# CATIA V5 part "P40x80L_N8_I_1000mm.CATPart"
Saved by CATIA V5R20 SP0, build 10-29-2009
Part number: 80x40_Y-Traeger
Nomenclature: P40x80L_N8_I
Source: Unknown
Bounding box of the stored display mesh (mm): x -25.6 to 54.4, y 0 to 40, z 80 to 1000
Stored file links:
  C:\Users\Andi\Desktop\Offene Projekte\Plasmacutter\Rahmen\P40x80L_N8_I_1000mm.CATPart
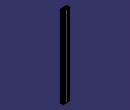
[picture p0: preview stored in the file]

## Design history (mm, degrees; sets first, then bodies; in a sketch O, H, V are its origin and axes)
Set1
  Sketch1 on face of Solid1, origin (0, 0, 0), H (1, 0, 0), V (0, -1, 0)
    projected arc E1 centre (2, -35.5) radius 2.5 from (2, -38) to (4.5, -35.5) ccw from edge [face of Solid1 | face of Solid1]
    projected arc E2 centre (2, -37.5) radius 0.5 from (1.5, -37.5) to (2, -38) ccw from edge [face of Solid1 | face of Solid1]
    projected line E3 (1.5, -35.85) -> (1.5, -37.5) from edge [face of Solid1 | face of Solid1]
    projected arc E4 centre (1, -35.85) radius 0.5 from (1.5, -35.85) to (1, -35.35) ccw from edge [face of Solid1 | face of Solid1]
    projected line E5 (-0.5, -35.35) -> (1, -35.35) from edge [face of Solid1 | face of Solid1]
    projected arc E6 centre (-0.5, -36.35) radius 1 from (-0.5, -35.35) to (-1.5, -36.35) ccw from edge [face of Solid1 | face of Solid1]
    projected line E7 (-1.5, -38.5) -> (-1.5, -36.35) from edge [face of Solid1 | face of Solid1]
    projected arc E8 centre (0, -38.5) radius 1.5 from (-1.5, -38.5) to (0, -40) ccw from edge [face of Solid1 | face of Solid1]
    projected line E9 (28.8, -40) -> (0, -40) from edge [face of Solid1 | face of Solid1]
    projected arc E10 centre (28.8, -38.5) radius 1.5 from (28.8, -40) to (30.3, -38.5) ccw from edge [face of Solid1 | face of Solid1]
    projected line E11 (30.3, -36.35) -> (30.3, -38.5) from edge [face of Solid1 | face of Solid1]
    projected arc E12 centre (29.3, -36.35) radius 1 from (30.3, -36.35) to (29.3, -35.35) ccw from edge [face of Solid1 | face of Solid1]
    projected line E13 (27.8, -35.35) -> (29.3, -35.35) from edge [face of Solid1 | face of Solid1]
    projected arc E14 centre (27.8, -35.85) radius 0.5 from (27.8, -35.35) to (27.3, -35.85) ccw from edge [face of Solid1 | face of Solid1]
    projected line E15 (27.3, -37.5) -> (27.3, -35.85) from edge [face of Solid1 | face of Solid1]
    projected arc E16 centre (26.8, -37.5) radius 0.5 from (26.8, -38) to (27.3, -37.5) ccw from edge [face of Solid1 | face of Solid1]
    projected arc E17 centre (26.8, -35.5) radius 2.5 from (24.3, -35.5) to (26.8, -38) ccw from edge [face of Solid1 | face of Solid1]
    projected line E18 (24.3, -34.2924) -> (24.3, -35.5) from edge [face of Solid1 | face of Solid1]
    projected arc E19 centre (29.3, -34.2924) radius 5 from (25.7645, -30.7569) to (24.3, -34.2924) ccw from edge [face of Solid1 | face of Solid1]
    projected line E20 (27.4569, -29.0645) -> (25.7645, -30.7569) from edge [face of Solid1 | face of Solid1]
    projected arc E21 centre (30.9924, -32.6) radius 5 from (30.9924, -27.6) to (27.4569, -29.0645) ccw from edge [face of Solid1 | face of Solid1]
    projected line E22 (37.8076, -27.6) -> (30.9924, -27.6) from edge [face of Solid1 | face of Solid1]
    projected arc E23 centre (37.8076, -32.6) radius 5 from (41.3431, -29.0645) to (37.8076, -27.6) ccw from edge [face of Solid1 | face of Solid1]
    projected line E24 (43.0355, -30.7569) -> (41.3431, -29.0645) from edge [face of Solid1 | face of Solid1]
    projected arc E25 centre (39.5, -34.2924) radius 5 from (44.5, -34.2924) to (43.0355, -30.7569) ccw from edge [face of Solid1 | face of Solid1]
    projected line E26 (44.5, -35.5) -> (44.5, -34.2924) from edge [face of Solid1 | face of Solid1]
    projected arc E27 centre (42, -35.5) radius 2.5 from (42, -38) to (44.5, -35.5) ccw from edge [face of Solid1 | face of Solid1]
    projected arc E28 centre (42, -37.5) radius 0.5 from (41.5, -37.5) to (42, -38) ccw from edge [face of Solid1 | face of Solid1]
    projected line E29 (41.5, -35.85) -> (41.5, -37.5) from edge [face of Solid1 | face of Solid1]
    projected arc E30 centre (41, -35.85) radius 0.5 from (41.5, -35.85) to (41, -35.35) ccw from edge [face of Solid1 | face of Solid1]
    projected line E31 (39.5, -35.35) -> (41, -35.35) from edge [face of Solid1 | face of Solid1]
    projected arc E32 centre (39.5, -36.35) radius 1 from (39.5, -35.35) to (38.5, -36.35) ccw from edge [face of Solid1 | face of Solid1]
    projected line E33 (38.5, -38.5) -> (38.5, -36.35) from edge [face of Solid1 | face of Solid1]
    projected arc E34 centre (40, -38.5) radius 1.5 from (38.5, -38.5) to (40, -40) ccw from edge [face of Solid1 | face of Solid1]
    projected line E35 (50.4, -40) -> (40, -40) from edge [face of Solid1 | face of Solid1]
    projected arc E36 centre (50.4, -36) radius 4 from (50.4, -40) to (54.4, -36) ccw from edge [face of Solid1 | face of Solid1]
    projected line E37 (54.4, -25.6) -> (54.4, -36) from edge [face of Solid1 | face of Solid1]
    projected arc E38 centre (52.9, -25.6) radius 1.5 from (54.4, -25.6) to (52.9, -24.1) ccw from edge [face of Solid1 | face of Solid1]
    projected line E39 (50.75, -24.1) -> (52.9, -24.1) from edge [face of Solid1 | face of Solid1]
    projected arc E40 centre (50.75, -25.1) radius 1 from (50.75, -24.1) to (49.75, -25.1) ccw from edge [face of Solid1 | face of Solid1]
    projected line E41 (49.75, -26.6) -> (49.75, -25.1) from edge [face of Solid1 | face of Solid1]
    projected arc E42 centre (50.25, -26.6) radius 0.5 from (49.75, -26.6) to (50.25, -27.1) ccw from edge [face of Solid1 | face of Solid1]
    projected line E43 (51.9, -27.1) -> (50.25, -27.1) from edge [face of Solid1 | face of Solid1]
    projected arc E44 centre (51.9, -27.6) radius 0.5 from (52.4, -27.6) to (51.9, -27.1) ccw from edge [face of Solid1 | face of Solid1]
    projected arc E45 centre (49.9, -27.6) radius 2.5 from (49.9, -30.1) to (52.4, -27.6) ccw from edge [face of Solid1 | face of Solid1]
    projected line E46 (48.6924, -30.1) -> (49.9, -30.1) from edge [face of Solid1 | face of Solid1]
    projected arc E47 centre (48.6924, -25.1) radius 5 from (45.1569, -28.6355) to (48.6924, -30.1) ccw from edge [face of Solid1 | face of Solid1]
    projected line E48 (43.4645, -26.9431) -> (45.1569, -28.6355) from edge [face of Solid1 | face of Solid1]
    projected arc E49 centre (47, -23.4076) radius 5 from (42, -23.4076) to (43.4645, -26.9431) ccw from edge [face of Solid1 | face of Solid1]
    projected line E50 (42, -16.5924) -> (42, -23.4076) from edge [face of Solid1 | face of Solid1]
    projected arc E51 centre (47, -16.5924) radius 5 from (43.4645, -13.0569) to (42, -16.5924) ccw from edge [face of Solid1 | face of Solid1]
    projected line E52 (45.1569, -11.3645) -> (43.4645, -13.0569) from edge [face of Solid1 | face of Solid1]
    projected arc E53 centre (48.6924, -14.9) radius 5 from (48.6924, -9.9) to (45.1569, -11.3645) ccw from edge [face of Solid1 | face of Solid1]
    projected line E54 (49.9, -9.9) -> (48.6924, -9.9) from edge [face of Solid1 | face of Solid1]
    projected arc E55 centre (49.9, -12.4) radius 2.5 from (52.4, -12.4) to (49.9, -9.9) ccw from edge [face of Solid1 | face of Solid1]
    projected arc E56 centre (51.9, -12.4) radius 0.5 from (51.9, -12.9) to (52.4, -12.4) ccw from edge [face of Solid1 | face of Solid1]
    projected line E57 (50.25, -12.9) -> (51.9, -12.9) from edge [face of Solid1 | face of Solid1]
    projected arc E58 centre (50.25, -13.4) radius 0.5 from (50.25, -12.9) to (49.75, -13.4) ccw from edge [face of Solid1 | face of Solid1]
    projected line E59 (49.75, -14.9) -> (49.75, -13.4) from edge [face of Solid1 | face of Solid1]
    projected arc E60 centre (50.75, -14.9) radius 1 from (49.75, -14.9) to (50.75, -15.9) ccw from edge [face of Solid1 | face of Solid1]
    projected line E61 (52.9, -15.9) -> (50.75, -15.9) from edge [face of Solid1 | face of Solid1]
    projected arc E62 centre (52.9, -14.4) radius 1.5 from (52.9, -15.9) to (54.4, -14.4) ccw from edge [face of Solid1 | face of Solid1]
    projected line E63 (54.4, -4) -> (54.4, -14.4) from edge [face of Solid1 | face of Solid1]
    projected arc E64 centre (50.4, -4) radius 4 from (54.4, -4) to (50.4, 0) ccw from edge [face of Solid1 | face of Solid1]
    projected line E65 (40, 0) -> (50.4, 0) from edge [face of Solid1 | face of Solid1]
    projected arc E66 centre (40, -1.5) radius 1.5 from (40, 0) to (38.5, -1.5) ccw from edge [face of Solid1 | face of Solid1]
    projected line E67 (38.5, -3.65) -> (38.5, -1.5) from edge [face of Solid1 | face of Solid1]
    projected arc E68 centre (39.5, -3.65) radius 1 from (38.5, -3.65) to (39.5, -4.65) ccw from edge [face of Solid1 | face of Solid1]
    projected line E69 (41, -4.65) -> (39.5, -4.65) from edge [face of Solid1 | face of Solid1]
    projected arc E70 centre (41, -4.15) radius 0.5 from (41, -4.65) to (41.5, -4.15) ccw from edge [face of Solid1 | face of Solid1]
    projected line E71 (41.5, -2.5) -> (41.5, -4.15) from edge [face of Solid1 | face of Solid1]
    projected arc E72 centre (42, -2.5) radius 0.5 from (42, -2) to (41.5, -2.5) ccw from edge [face of Solid1 | face of Solid1]
    projected arc E73 centre (42, -4.5) radius 2.5 from (44.5, -4.5) to (42, -2) ccw from edge [face of Solid1 | face of Solid1]
    projected line E74 (44.5, -5.7076) -> (44.5, -4.5) from edge [face of Solid1 | face of Solid1]
    projected arc E75 centre (39.5, -5.7076) radius 5 from (43.0355, -9.2431) to (44.5, -5.7076) ccw from edge [face of Solid1 | face of Solid1]
    projected line E76 (41.3431, -10.9355) -> (43.0355, -9.2431) from edge [face of Solid1 | face of Solid1]
    projected arc E77 centre (37.8076, -7.4) radius 5 from (37.8076, -12.4) to (41.3431, -10.9355) ccw from edge [face of Solid1 | face of Solid1]
    projected line E78 (30.9924, -12.4) -> (37.8076, -12.4) from edge [face of Solid1 | face of Solid1]
    projected arc E79 centre (30.9924, -7.4) radius 5 from (27.4569, -10.9355) to (30.9924, -12.4) ccw from edge [face of Solid1 | face of Solid1]
    projected line E80 (25.7645, -9.2431) -> (27.4569, -10.9355) from edge [face of Solid1 | face of Solid1]
    projected arc E81 centre (29.3, -5.7076) radius 5 from (24.3, -5.7076) to (25.7645, -9.2431) ccw from edge [face of Solid1 | face of Solid1]
    projected line E82 (24.3, -4.5) -> (24.3, -5.7076) from edge [face of Solid1 | face of Solid1]
    projected arc E83 centre (26.8, -4.5) radius 2.5 from (26.8, -2) to (24.3, -4.5) ccw from edge [face of Solid1 | face of Solid1]
    projected arc E84 centre (26.8, -2.5) radius 0.5 from (27.3, -2.5) to (26.8, -2) ccw from edge [face of Solid1 | face of Solid1]
    projected line E85 (27.3, -4.15) -> (27.3, -2.5) from edge [face of Solid1 | face of Solid1]
    projected arc E86 centre (27.8, -4.15) radius 0.5 from (27.3, -4.15) to (27.8, -4.65) ccw from edge [face of Solid1 | face of Solid1]
    projected line E87 (29.3, -4.65) -> (27.8, -4.65) from edge [face of Solid1 | face of Solid1]
    projected arc E88 centre (29.3, -3.65) radius 1 from (29.3, -4.65) to (30.3, -3.65) ccw from edge [face of Solid1 | face of Solid1]
    projected line E89 (30.3, -1.5) -> (30.3, -3.65) from edge [face of Solid1 | face of Solid1]
    projected arc E90 centre (28.8, -1.5) radius 1.5 from (30.3, -1.5) to (28.8, 0) ccw from edge [face of Solid1 | face of Solid1]
    projected line E91 (0, 0) -> (28.8, 0) from edge [face of Solid1 | face of Solid1]
    projected arc E92 centre (0, -1.5) radius 1.5 from (0, 0) to (-1.5, -1.5) ccw from edge [face of Solid1 | face of Solid1]
    projected line E93 (-1.5, -3.65) -> (-1.5, -1.5) from edge [face of Solid1 | face of Solid1]
    projected arc E94 centre (-0.5, -3.65) radius 1 from (-1.5, -3.65) to (-0.5, -4.65) ccw from edge [face of Solid1 | face of Solid1]
    projected line E95 (1, -4.65) -> (-0.5, -4.65) from edge [face of Solid1 | face of Solid1]
    projected arc E96 centre (1, -4.15) radius 0.5 from (1, -4.65) to (1.5, -4.15) ccw from edge [face of Solid1 | face of Solid1]
    projected line E97 (1.5, -2.5) -> (1.5, -4.15) from edge [face of Solid1 | face of Solid1]
    projected arc E98 centre (2, -2.5) radius 0.5 from (2, -2) to (1.5, -2.5) ccw from edge [face of Solid1 | face of Solid1]
    projected arc E99 centre (2, -4.5) radius 2.5 from (4.5, -4.5) to (2, -2) ccw from edge [face of Solid1 | face of Solid1]
    projected line E100 (4.5, -5.7076) -> (4.5, -4.5) from edge [face of Solid1 | face of Solid1]
    projected arc E101 centre (-0.5, -5.7076) radius 5 from (3.0355, -9.2431) to (4.5, -5.7076) ccw from edge [face of Solid1 | face of Solid1]
    projected line E102 (1.3431, -10.9355) -> (3.0355, -9.2431) from edge [face of Solid1 | face of Solid1]
    projected arc E103 centre (-2.1924, -7.4) radius 5 from (-2.1924, -12.4) to (1.3431, -10.9355) ccw from edge [face of Solid1 | face of Solid1]
    projected line E104 (-9.0076, -12.4) -> (-2.1924, -12.4) from edge [face of Solid1 | face of Solid1]
    projected arc E105 centre (-9.0076, -7.4) radius 5 from (-12.5431, -10.9355) to (-9.0076, -12.4) ccw from edge [face of Solid1 | face of Solid1]
    projected line E106 (-14.2355, -9.2431) -> (-12.5431, -10.9355) from edge [face of Solid1 | face of Solid1]
    projected arc E107 centre (-10.7, -5.7076) radius 5 from (-15.7, -5.7076) to (-14.2355, -9.2431) ccw from edge [face of Solid1 | face of Solid1]
    projected line E108 (-15.7, -4.5) -> (-15.7, -5.7076) from edge [face of Solid1 | face of Solid1]
    projected arc E109 centre (-13.2, -4.5) radius 2.5 from (-13.2, -2) to (-15.7, -4.5) ccw from edge [face of Solid1 | face of Solid1]
    projected arc E110 centre (-13.2, -2.5) radius 0.5 from (-12.7, -2.5) to (-13.2, -2) ccw from edge [face of Solid1 | face of Solid1]
    projected line E111 (-12.7, -4.15) -> (-12.7, -2.5) from edge [face of Solid1 | face of Solid1]
    projected arc E112 centre (-12.2, -4.15) radius 0.5 from (-12.7, -4.15) to (-12.2, -4.65) ccw from edge [face of Solid1 | face of Solid1]
    projected line E113 (-10.7, -4.65) -> (-12.2, -4.65) from edge [face of Solid1 | face of Solid1]
    projected arc E114 centre (-10.7, -3.65) radius 1 from (-10.7, -4.65) to (-9.7, -3.65) ccw from edge [face of Solid1 | face of Solid1]
    projected line E115 (-9.7, -1.5) -> (-9.7, -3.65) from edge [face of Solid1 | face of Solid1]
    projected arc E116 centre (-11.2, -1.5) radius 1.5 from (-9.7, -1.5) to (-11.2, 0) ccw from edge [face of Solid1 | face of Solid1]
    projected line E117 (-21.6, 0) -> (-11.2, 0) from edge [face of Solid1 | face of Solid1]
    projected arc E118 centre (-21.6, -4) radius 4 from (-21.6, 0) to (-25.6, -4) ccw from edge [face of Solid1 | face of Solid1]
    projected line E119 (-25.6, -14.4) -> (-25.6, -4) from edge [face of Solid1 | face of Solid1]
    projected arc E120 centre (-24.1, -14.4) radius 1.5 from (-25.6, -14.4) to (-24.1, -15.9) ccw from edge [face of Solid1 | face of Solid1]
    projected line E121 (-21.95, -15.9) -> (-24.1, -15.9) from edge [face of Solid1 | face of Solid1]
    projected arc E122 centre (-21.95, -14.9) radius 1 from (-21.95, -15.9) to (-20.95, -14.9) ccw from edge [face of Solid1 | face of Solid1]
    projected line E123 (-20.95, -13.4) -> (-20.95, -14.9) from edge [face of Solid1 | face of Solid1]
    projected arc E124 centre (-21.45, -13.4) radius 0.5 from (-20.95, -13.4) to (-21.45, -12.9) ccw from edge [face of Solid1 | face of Solid1]
    projected line E125 (-23.1, -12.9) -> (-21.45, -12.9) from edge [face of Solid1 | face of Solid1]
    projected arc E126 centre (-23.1, -12.4) radius 0.5 from (-23.6, -12.4) to (-23.1, -12.9) ccw from edge [face of Solid1 | face of Solid1]
    projected arc E127 centre (-21.1, -12.4) radius 2.5 from (-21.1, -9.9) to (-23.6, -12.4) ccw from edge [face of Solid1 | face of Solid1]
    projected line E128 (-19.8924, -9.9) -> (-21.1, -9.9) from edge [face of Solid1 | face of Solid1]
    projected arc E129 centre (-19.8924, -14.9) radius 5 from (-16.3569, -11.3645) to (-19.8924, -9.9) ccw from edge [face of Solid1 | face of Solid1]
    projected line E130 (-14.6645, -13.0569) -> (-16.3569, -11.3645) from edge [face of Solid1 | face of Solid1]
    projected arc E131 centre (-18.2, -16.5924) radius 5 from (-13.2, -16.5924) to (-14.6645, -13.0569) ccw from edge [face of Solid1 | face of Solid1]
    projected line E132 (-13.2, -23.4076) -> (-13.2, -16.5924) from edge [face of Solid1 | face of Solid1]
    projected arc E133 centre (-18.2, -23.4076) radius 5 from (-14.6645, -26.9431) to (-13.2, -23.4076) ccw from edge [face of Solid1 | face of Solid1]
    projected line E134 (-16.3569, -28.6355) -> (-14.6645, -26.9431) from edge [face of Solid1 | face of Solid1]
    projected arc E135 centre (-19.8924, -25.1) radius 5 from (-19.8924, -30.1) to (-16.3569, -28.6355) ccw from edge [face of Solid1 | face of Solid1]
    projected line E136 (-21.1, -30.1) -> (-19.8924, -30.1) from edge [face of Solid1 | face of Solid1]
    projected arc E137 centre (-21.1, -27.6) radius 2.5 from (-23.6, -27.6) to (-21.1, -30.1) ccw from edge [face of Solid1 | face of Solid1]
    projected arc E138 centre (-23.1, -27.6) radius 0.5 from (-23.1, -27.1) to (-23.6, -27.6) ccw from edge [face of Solid1 | face of Solid1]
    projected line E139 (-21.45, -27.1) -> (-23.1, -27.1) from edge [face of Solid1 | face of Solid1]
    projected arc E140 centre (-21.45, -26.6) radius 0.5 from (-21.45, -27.1) to (-20.95, -26.6) ccw from edge [face of Solid1 | face of Solid1]
    projected line E141 (-20.95, -25.1) -> (-20.95, -26.6) from edge [face of Solid1 | face of Solid1]
    projected arc E142 centre (-21.95, -25.1) radius 1 from (-20.95, -25.1) to (-21.95, -24.1) ccw from edge [face of Solid1 | face of Solid1]
    projected line E143 (-24.1, -24.1) -> (-21.95, -24.1) from edge [face of Solid1 | face of Solid1]
    projected arc E144 centre (-24.1, -25.6) radius 1.5 from (-24.1, -24.1) to (-25.6, -25.6) ccw from edge [face of Solid1 | face of Solid1]
    projected line E145 (-25.6, -36) -> (-25.6, -25.6) from edge [face of Solid1 | face of Solid1]
    projected arc E146 centre (-21.6, -36) radius 4 from (-25.6, -36) to (-21.6, -40) ccw from edge [face of Solid1 | face of Solid1]
    projected line E147 (-11.2, -40) -> (-21.6, -40) from edge [face of Solid1 | face of Solid1]
    projected arc E148 centre (-11.2, -38.5) radius 1.5 from (-11.2, -40) to (-9.7, -38.5) ccw from edge [face of Solid1 | face of Solid1]
    projected line E149 (-9.7, -36.35) -> (-9.7, -38.5) from edge [face of Solid1 | face of Solid1]
    projected arc E150 centre (-10.7, -36.35) radius 1 from (-9.7, -36.35) to (-10.7, -35.35) ccw from edge [face of Solid1 | face of Solid1]
    projected line E151 (-12.2, -35.35) -> (-10.7, -35.35) from edge [face of Solid1 | face of Solid1]
    projected arc E152 centre (-12.2, -35.85) radius 0.5 from (-12.2, -35.35) to (-12.7, -35.85) ccw from edge [face of Solid1 | face of Solid1]
    projected line E153 (-12.7, -37.5) -> (-12.7, -35.85) from edge [face of Solid1 | face of Solid1]
    projected arc E154 centre (-13.2, -37.5) radius 0.5 from (-13.2, -38) to (-12.7, -37.5) ccw from edge [face of Solid1 | face of Solid1]
    projected arc E155 centre (-13.2, -35.5) radius 2.5 from (-15.7, -35.5) to (-13.2, -38) ccw from edge [face of Solid1 | face of Solid1]
    projected line E156 (-15.7, -34.2924) -> (-15.7, -35.5) from edge [face of Solid1 | face of Solid1]
    projected arc E157 centre (-10.7, -34.2924) radius 5 from (-14.2355, -30.7569) to (-15.7, -34.2924) ccw from edge [face of Solid1 | face of Solid1]
    projected line E158 (-12.5431, -29.0645) -> (-14.2355, -30.7569) from edge [face of Solid1 | face of Solid1]
    projected arc E159 centre (-9.0076, -32.6) radius 5 from (-9.0076, -27.6) to (-12.5431, -29.0645) ccw from edge [face of Solid1 | face of Solid1]
    projected line E160 (-2.1924, -27.6) -> (-9.0076, -27.6) from edge [face of Solid1 | face of Solid1]
    projected arc E161 centre (-2.1924, -32.6) radius 5 from (1.3431, -29.0645) to (-2.1924, -27.6) ccw from edge [face of Solid1 | face of Solid1]
    projected line E162 (3.0355, -30.7569) -> (1.3431, -29.0645) from edge [face of Solid1 | face of Solid1]
    projected arc E163 centre (-0.5, -34.2924) radius 5 from (4.5, -34.2924) to (3.0355, -30.7569) ccw from edge [face of Solid1 | face of Solid1]
    projected line E164 (4.5, -35.5) -> (4.5, -34.2924) from edge [face of Solid1 | face of Solid1]
    projected arc E165 centre (1.2, -8.2503) radius 5 from (4.7355, -11.7858) to (6.2, -8.2503) ccw from edge [face of Solid1 | face of Solid1]
    projected line E166 (6.2, -8.2503) -> (6.2, -4.5) from edge [face of Solid1 | face of Solid1]
    projected arc E167 centre (8.7, -4.5) radius 2.5 from (8.7, -2) to (6.2, -4.5) ccw from edge [face of Solid1 | face of Solid1]
    projected line E168 (8.7, -2) -> (20.1, -2) from edge [face of Solid1 | face of Solid1]
    projected arc E169 centre (20.1, -4.5) radius 2.5 from (22.6, -4.5) to (20.1, -2) ccw from edge [face of Solid1 | face of Solid1]
    projected line E170 (22.6, -4.5) -> (22.6, -8.2503) from edge [face of Solid1 | face of Solid1]
    projected arc E171 centre (27.6, -8.2503) radius 5 from (22.6, -8.2503) to (24.0645, -11.7858) ccw from edge [face of Solid1 | face of Solid1]
    projected line E172 (24.0645, -11.7858) -> (25.1855, -12.9069) from edge [face of Solid1 | face of Solid1]
    projected arc E173 centre (21.65, -16.4424) radius 5 from (26.65, -16.4424) to (25.1855, -12.9069) ccw from edge [face of Solid1 | face of Solid1]
    projected line E174 (26.65, -16.4424) -> (26.65, -23.5576) from edge [face of Solid1 | face of Solid1]
    projected arc E175 centre (21.65, -23.5576) radius 5 from (25.1855, -27.0931) to (26.65, -23.5576) ccw from edge [face of Solid1 | face of Solid1]
    projected line E176 (25.1855, -27.0931) -> (24.0645, -28.2142) from edge [face of Solid1 | face of Solid1]
    projected arc E177 centre (27.6, -31.7497) radius 5 from (24.0645, -28.2142) to (22.6, -31.7497) ccw from edge [face of Solid1 | face of Solid1]
    projected line E178 (22.6, -31.7497) -> (22.6, -35.5) from edge [face of Solid1 | face of Solid1]
    projected arc E179 centre (20.1, -35.5) radius 2.5 from (20.1, -38) to (22.6, -35.5) ccw from edge [face of Solid1 | face of Solid1]
    projected line E180 (20.1, -38) -> (8.7, -38) from edge [face of Solid1 | face of Solid1]
    projected arc E181 centre (8.7, -35.5) radius 2.5 from (6.2, -35.5) to (8.7, -38) ccw from edge [face of Solid1 | face of Solid1]
    projected line E182 (6.2, -35.5) -> (6.2, -31.7497) from edge [face of Solid1 | face of Solid1]
    projected arc E183 centre (1.2, -31.7497) radius 5 from (6.2, -31.7497) to (4.7355, -28.2142) ccw from edge [face of Solid1 | face of Solid1]
    projected line E184 (4.7355, -28.2142) -> (3.6145, -27.0931) from edge [face of Solid1 | face of Solid1]
    projected arc E185 centre (7.15, -23.5576) radius 5 from (2.15, -23.5576) to (3.6145, -27.0931) ccw from edge [face of Solid1 | face of Solid1]
    projected line E186 (2.15, -23.5576) -> (2.15, -16.4424) from edge [face of Solid1 | face of Solid1]
    projected arc E187 centre (7.15, -16.4424) radius 5 from (3.6145, -12.9069) to (2.15, -16.4424) ccw from edge [face of Solid1 | face of Solid1]
    projected line E188 (3.6145, -12.9069) -> (4.7355, -11.7858) from edge [face of Solid1 | face of Solid1]
    projected arc E189 centre (-23.3, -7.7) radius 0.5 from (-23.8, -7.7) to (-23.3, -8.2) ccw from edge [face of Solid1 | face of Solid1]
    projected line E190 (-23.8, -7.7) -> (-23.8, -4) from edge [face of Solid1 | face of Solid1]
    projected arc E191 centre (-21.6, -4) radius 2.2 from (-21.6, -1.8) to (-23.8, -4) ccw from edge [face of Solid1 | face of Solid1]
    projected line E192 (-21.6, -1.8) -> (-17.9, -1.8) from edge [face of Solid1 | face of Solid1]
    projected arc E193 centre (-17.9, -2.3) radius 0.5 from (-17.4, -2.3) to (-17.9, -1.8) ccw from edge [face of Solid1 | face of Solid1]
    projected line E194 (-17.4, -2.3) -> (-17.4, -7.7) from edge [face of Solid1 | face of Solid1]
    projected arc E195 centre (-17.9, -7.7) radius 0.5 from (-17.9, -8.2) to (-17.4, -7.7) ccw from edge [face of Solid1 | face of Solid1]
    projected line E196 (-17.9, -8.2) -> (-23.3, -8.2) from edge [face of Solid1 | face of Solid1]
    projected arc E197 centre (-17.9, -37.7) radius 0.5 from (-17.9, -38.2) to (-17.4, -37.7) ccw from edge [face of Solid1 | face of Solid1]
    projected line E198 (-17.9, -38.2) -> (-21.6, -38.2) from edge [face of Solid1 | face of Solid1]
    projected arc E199 centre (-21.6, -36) radius 2.2 from (-23.8, -36) to (-21.6, -38.2) ccw from edge [face of Solid1 | face of Solid1]
    projected line E200 (-23.8, -36) -> (-23.8, -32.3) from edge [face of Solid1 | face of Solid1]
    projected arc E201 centre (-23.3, -32.3) radius 0.5 from (-23.3, -31.8) to (-23.8, -32.3) ccw from edge [face of Solid1 | face of Solid1]
    projected line E202 (-23.3, -31.8) -> (-17.9, -31.8) from edge [face of Solid1 | face of Solid1]
    projected arc E203 centre (-17.9, -32.3) radius 0.5 from (-17.4, -32.3) to (-17.9, -31.8) ccw from edge [face of Solid1 | face of Solid1]
    projected line E204 (-17.4, -32.3) -> (-17.4, -37.7) from edge [face of Solid1 | face of Solid1]
    projected arc E205 centre (52.1, -7.7) radius 0.5 from (52.1, -8.2) to (52.6, -7.7) ccw from edge [face of Solid1 | face of Solid1]
    projected line E206 (52.1, -8.2) -> (46.7, -8.2) from edge [face of Solid1 | face of Solid1]
    projected arc E207 centre (46.7, -7.7) radius 0.5 from (46.2, -7.7) to (46.7, -8.2) ccw from edge [face of Solid1 | face of Solid1]
    projected line E208 (46.2, -7.7) -> (46.2, -2.3) from edge [face of Solid1 | face of Solid1]
    projected arc E209 centre (46.7, -2.3) radius 0.5 from (46.7, -1.8) to (46.2, -2.3) ccw from edge [face of Solid1 | face of Solid1]
    projected line E210 (46.7, -1.8) -> (50.4, -1.8) from edge [face of Solid1 | face of Solid1]
    projected arc E211 centre (50.4, -4) radius 2.2 from (52.6, -4) to (50.4, -1.8) ccw from edge [face of Solid1 | face of Solid1]
    projected line E212 (52.6, -4) -> (52.6, -7.7) from edge [face of Solid1 | face of Solid1]
    projected arc E213 centre (46.7, -37.7) radius 0.5 from (46.2, -37.7) to (46.7, -38.2) ccw from edge [face of Solid1 | face of Solid1]
    projected line E214 (46.2, -37.7) -> (46.2, -32.3) from edge [face of Solid1 | face of Solid1]
    projected arc E215 centre (46.7, -32.3) radius 0.5 from (46.7, -31.8) to (46.2, -32.3) ccw from edge [face of Solid1 | face of Solid1]
    projected line E216 (46.7, -31.8) -> (52.1, -31.8) from edge [face of Solid1 | face of Solid1]
    projected arc E217 centre (52.1, -32.3) radius 0.5 from (52.6, -32.3) to (52.1, -31.8) ccw from edge [face of Solid1 | face of Solid1]
    projected line E218 (52.6, -32.3) -> (52.6, -36) from edge [face of Solid1 | face of Solid1]
    projected arc E219 centre (50.4, -36) radius 2.2 from (50.4, -38.2) to (52.6, -36) ccw from edge [face of Solid1 | face of Solid1]
    projected line E220 (50.4, -38.2) -> (46.7, -38.2) from edge [face of Solid1 | face of Solid1]
    projected arc E221 centre (34.4, -20) radius 3.35 from (31.05, -20) to (37.75, -20) ccw from edge [face of Solid1 | face of Solid1]
    projected arc E222 centre (34.4, -20) radius 3.35 from (37.75, -20) to (31.05, -20) ccw from edge [face of Solid1 | face of Solid1]
    projected arc E223 centre (-5.6, -20) radius 3.35 from (-8.95, -20) to (-2.25, -20) ccw from edge [face of Solid1 | face of Solid1]
    projected arc E224 centre (-5.6, -20) radius 3.35 from (-2.25, -20) to (-8.95, -20) ccw from edge [face of Solid1 | face of Solid1]
Body1 "MANIFOLD_SOLID_BREP #7665" (main body)
  Solid1: solid without history
  Pocket1: profile Sketch1, direction (0, 0, 1), length 80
